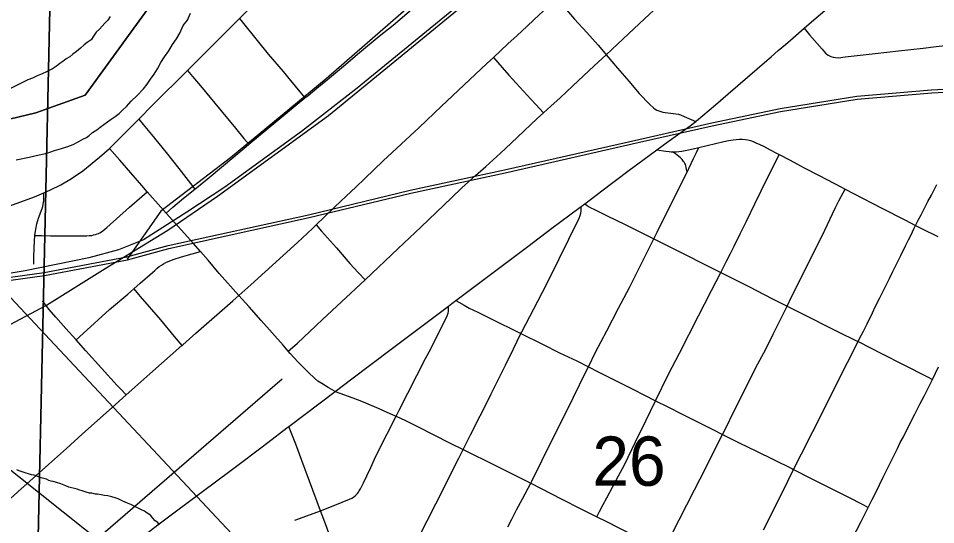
# Model space of a CAD drawing. Extents: x 0 to 34, y 0 to 22.
# Drawn here: x 5.405 to 6.184, y 17.843 to 18.273 of the extents above; entities that cross this region are included whole.
import ezdxf

# ---------------------------------------------------------------- set-up
doc = ezdxf.new("R2010")
doc.units = 0
for name, color, linetype in [('GM_X_City_Street', 7, 'Continuous'), ('GM_X_County_Road', 7, 'Continuous'), ('GM_X_Major_River', 7, 'Continuous'), ('GM_X_Minor_River', 7, 'Continuous'), ('GM_X_Rail_Line', 7, 'Continuous'), ('GM_X_Section', 7, 'Continuous'), ('GM_X_Section_Text', 7, 'Continuous'), ('GM_X_State_Route', 7, 'Continuous'), ('GM_X_Township_Road', 7, 'Continuous'), ('SH_Text', 7, 'Continuous')]:
    doc.layers.add(name, color=color, linetype=linetype)

msp = doc.modelspace()

# ---------------------------------------------------------------- linework, layer by layer
at = {"layer": 'GM_X_City_Street'}
msp.add_line((5.48249, 18.16259), (5.50731, 18.18755), dxfattribs=at)
for points in [[(5.59291, 18.27288), (5.59552, 18.2755), (5.60608, 18.28599), (5.62442, 18.30455), (5.63292, 18.31275), (5.64184, 18.32135), (5.65835, 18.33812), (5.66747, 18.34738), (5.67636, 18.35627)], [(5.59248, 18.03782), (5.60256, 18.04679), (5.64216, 18.0827), (5.65479, 18.09465), (5.65798, 18.09772), (5.66509, 18.10454), (5.67403, 18.11317), (5.68349, 18.12213), (5.69171, 18.12987), (5.69952, 18.13711), (5.71503, 18.15208), (5.7455, 18.18048), (5.7644, 18.19847), (5.80287, 18.23437), (5.80869, 18.23986), (5.82096, 18.25144), (5.82871, 18.25859), (5.83691, 18.26609), (5.84317, 18.27203), (5.84727, 18.27575), (5.85443, 18.28252), (5.85622, 18.2842), (5.86229, 18.28992)], [(5.63431, 17.99043), (5.63979, 17.99526), (5.64213, 17.99732), (5.65266, 18.00702), (5.66356, 18.01721), (5.69953, 18.05091), (5.72782, 18.07778), (5.74686, 18.09566), (5.77331, 18.12104), (5.78185, 18.12918), (5.79333, 18.13962), (5.80223, 18.14738), (5.8146, 18.15867), (5.82363, 18.167), (5.84588, 18.18813), (5.85125, 18.19297), (5.8574, 18.19852), (5.86521, 18.20564), (5.87612, 18.21581), (5.88505, 18.2244), (5.89409, 18.2328), (5.9043, 18.24227), (5.91889, 18.2558), (5.93707, 18.27274), (5.96005, 18.29459)], [(5.53054, 18.10776), (5.53639, 18.11275), (5.54541, 18.12043), (5.55493, 18.12816), (5.56713, 18.13807), (5.59866, 18.16423), (5.60091, 18.16614), (5.62372, 18.18537), (5.64847, 18.20551), (5.65113, 18.20766), (5.6587, 18.21396), (5.66771, 18.2213), (5.68115, 18.23247), (5.6948, 18.24404), (5.71165, 18.25787), (5.72337, 18.26736), (5.73903, 18.28064)], [(5.86892, 18.28232), (5.87745, 18.27248), (5.88791, 18.26099), (5.89748, 18.25033), (5.9035, 18.24319), (5.9043, 18.24227), (5.91399, 18.23094), (5.91996, 18.22394), (5.92354, 18.21973), (5.93248, 18.20944), (5.94141, 18.19994), (5.94454, 18.19708), (5.94589, 18.19608), (5.94753, 18.19517), (5.94906, 18.19451), (5.95083, 18.19397), (5.95251, 18.19358), (5.95437, 18.19326), (5.96366, 18.19208), (5.96571, 18.19165), (5.96749, 18.19108), (5.97069, 18.18972), (5.98042, 18.18562)], [(5.54878, 18.22883), (5.56611, 18.246), (5.59291, 18.27288)], [(5.59291, 18.27288), (5.59637, 18.26863), (5.60807, 18.25431), (5.61737, 18.24263), (5.62994, 18.22797), (5.63624, 18.22024), (5.64404, 18.21084), (5.64847, 18.20551)], [(6.07262, 18.2647), (6.07723, 18.25926), (6.08774, 18.24688), (6.09083, 18.24363), (6.09288, 18.24199), (6.09524, 18.24067), (6.09714, 18.24006), (6.0991, 18.23975), (6.10168, 18.23971), (6.10736, 18.24036), (6.13276, 18.24319), (6.15257, 18.24547), (6.17363, 18.24785), (6.18475, 18.24916), (6.18981, 18.24985), (6.19176, 18.25019), (6.19348, 18.25077), (6.19532, 18.25204), (6.19693, 18.25353)], [(5.80869, 18.23986), (5.81593, 18.23148), (5.82157, 18.22494), (5.84028, 18.20444), (5.84452, 18.20001), (5.85125, 18.19297)], [(5.50731, 18.18755), (5.51929, 18.19961), (5.54878, 18.22883)], [(5.54878, 18.22883), (5.55297, 18.22387), (5.55978, 18.2158), (5.58954, 18.17972), (5.59674, 18.17113), (5.60091, 18.16614)], [(5.50731, 18.18755), (5.51101, 18.18311), (5.51817, 18.17453), (5.53068, 18.15916), (5.54147, 18.14552), (5.55136, 18.13277), (5.55493, 18.12816)], [(5.82084, 17.84123), (5.82419, 17.84783), (5.82834, 17.85566), (5.83323, 17.86489), (5.84029, 17.87822), (5.84127, 17.88006), (5.84987, 17.89744), (5.85944, 17.91679), (5.86833, 17.93474), (5.87658, 17.95142), (5.88724, 17.97296), (5.88928, 17.97708), (5.89544, 17.98954), (5.90492, 18.0077), (5.91489, 18.02688), (5.92411, 18.04464), (5.92838, 18.05301), (5.93424, 18.06446), (5.94487, 18.08579), (5.94779, 18.09163), (5.95799, 18.11223), (5.97307, 18.14244), (5.97456, 18.14561), (5.97852, 18.15396), (5.98102, 18.15924), (5.983, 18.16342)], [(5.9474, 18.16141), (5.95514, 18.16031), (5.95794, 18.15991), (5.95956, 18.15975), (5.96064, 18.15972), (5.96385, 18.15974), (5.96868, 18.16028), (5.97292, 18.16108), (5.97833, 18.16228), (5.983, 18.16342), (6.00433, 18.16862), (6.00832, 18.16947), (6.01236, 18.17008), (6.01484, 18.17037), (6.01742, 18.17045), (6.0199, 18.17044), (6.02252, 18.17019), (6.02479, 18.16982), (6.02691, 18.16925), (6.02924, 18.16847), (6.03166, 18.16752), (6.03485, 18.16602), (6.03792, 18.16453), (6.04357, 18.16157), (6.0492, 18.15862), (6.0514, 18.15747), (6.06075, 18.15257), (6.06946, 18.1479), (6.07269, 18.14618), (6.0853, 18.13954), (6.10432, 18.12974), (6.1075, 18.1281), (6.11448, 18.12449), (6.13865, 18.1118), (6.15796, 18.10189), (6.16721, 18.09728), (6.17236, 18.0947), (6.18616, 18.08791)], [(5.51461, 18.12582), (5.51, 18.1311), (5.49137, 18.15281), (5.48249, 18.16259)], [(5.89645, 17.8498), (5.89878, 17.85419), (5.90192, 17.86009), (5.90503, 17.86594), (5.90977, 17.87486), (5.91489, 17.88451), (5.91984, 17.89386), (5.92933, 17.91332), (5.93812, 17.93131), (5.94639, 17.94827), (5.95745, 17.97093), (5.96669, 17.98878), (5.9829, 18.02058), (5.98789, 18.03025), (5.99393, 18.042), (6.00184, 18.05736), (6.00674, 18.06689), (6.01011, 18.07342), (6.01319, 18.07965), (6.01828, 18.09013), (6.02354, 18.10094), (6.03072, 18.11572), (6.03595, 18.12649), (6.04084, 18.13655), (6.04841, 18.15155), (6.0514, 18.15747)], [(5.97307, 18.14244), (5.97264, 18.14479), (5.97228, 18.14676), (5.97198, 18.14795), (5.97168, 18.149), (5.97125, 18.14994), (5.97066, 18.15093), (5.97021, 18.15163), (5.9696, 18.15242), (5.96901, 18.15322), (5.96821, 18.15405), (5.96718, 18.15501), (5.96619, 18.15588), (5.96483, 18.15695), (5.96332, 18.15803), (5.96064, 18.15972)], [(5.41828, 18.06436), (5.41822, 18.06966), (5.41847, 18.07876), (5.41906, 18.08861), (5.41978, 18.09411), (5.42072, 18.09851), (5.4222, 18.10328), (5.42533, 18.11173), (5.42577, 18.11336), (5.42626, 18.11525), (5.42651, 18.11677), (5.42663, 18.11813), (5.42663, 18.11945), (5.42662, 18.12496)], [(5.41906, 18.08861), (5.42487, 18.08858), (5.43232, 18.08854), (5.46091, 18.08836), (5.46336, 18.08849), (5.46525, 18.08859), (5.46735, 18.08882), (5.46904, 18.08915), (5.47051, 18.08956), (5.47191, 18.09007), (5.47306, 18.09051), (5.47417, 18.09107), (5.47557, 18.09183), (5.47683, 18.09269), (5.48026, 18.09537), (5.49961, 18.11287), (5.50995, 18.1218), (5.51461, 18.12582)], [(5.53054, 18.10776), (5.52599, 18.11283), (5.51461, 18.12582)], [(5.95313, 17.82108), (5.95571, 17.8261), (5.95998, 17.83439), (5.97942, 17.87266), (5.98897, 17.89149), (5.99793, 17.9092), (6.00331, 17.9198), (6.00747, 17.92802), (6.01116, 17.93582), (6.01615, 17.94581), (6.0263, 17.96636), (6.03326, 17.97958), (6.03997, 17.99218), (6.04615, 18.00498), (6.04811, 18.00877), (6.05801, 18.02874), (6.06185, 18.03651), (6.08081, 18.07421), (6.09003, 18.09309), (6.09655, 18.10707), (6.09929, 18.1126), (6.10209, 18.11807), (6.10412, 18.12183), (6.1075, 18.1281)], [(6.038, 17.83868), (6.05394, 17.87018), (6.06363, 17.88984), (6.07031, 17.90338), (6.07987, 17.92232), (6.08916, 17.94074), (6.10044, 17.9631), (6.11832, 17.99855), (6.11967, 18.00122), (6.12295, 18.00746), (6.126, 18.01369), (6.13065, 18.0231), (6.13328, 18.0286), (6.13686, 18.03574), (6.1452, 18.05216), (6.14773, 18.05765), (6.14984, 18.06199), (6.15195, 18.06611), (6.15459, 18.07171), (6.15859, 18.07985), (6.16113, 18.08492), (6.16309, 18.08881), (6.16598, 18.09485), (6.16721, 18.09728), (6.16946, 18.10172), (6.17189, 18.10626), (6.17454, 18.1113), (6.17775, 18.11743), (6.18068, 18.12286), (6.18536, 18.132)], [(5.7451, 17.83202), (5.75959, 17.86084), (5.77927, 17.89954), (5.78294, 17.90685), (5.78928, 17.91948), (5.79745, 17.93551), (5.80301, 17.94656), (5.80679, 17.95432), (5.81308, 17.9671), (5.81876, 17.97864), (5.82558, 17.99251), (5.8319, 18.00534), (5.83272, 18.00701), (5.8462, 18.03288), (5.85415, 18.04833), (5.86443, 18.06884), (5.87258, 18.08558), (5.88147, 18.10329), (5.88241, 18.10569), (5.88281, 18.10752), (5.88316, 18.10947), (5.8831, 18.11196), (5.88306, 18.11335)], [(5.88622, 18.11569), (5.88837, 18.11416), (5.89008, 18.11301), (5.89181, 18.11202), (5.89329, 18.11126), (5.9051, 18.10551), (5.92045, 18.09803), (5.93987, 18.08834), (5.94487, 18.08579), (5.95271, 18.08177), (5.96703, 18.07471), (5.9922, 18.06222), (6.00184, 18.05736), (6.01147, 18.05252), (6.02611, 18.04497), (6.04504, 18.03528), (6.05801, 18.02874), (6.06821, 18.02361), (6.10143, 18.00687), (6.11701, 17.99921), (6.11832, 17.99855), (6.13885, 17.98813), (6.15662, 17.9791), (6.1772, 17.96858), (6.18146, 17.9664)], [(5.55974, 18.07515), (5.55344, 18.08232), (5.53596, 18.10172), (5.53054, 18.10776)], [(5.65798, 18.09772), (5.6626, 18.09248), (5.67532, 18.07808), (5.68675, 18.06499), (5.69383, 18.05718), (5.69953, 18.05091)], [(5.4541, 17.99999), (5.46008, 18.00541), (5.48258, 18.02571), (5.49795, 18.03897), (5.5032, 18.04346), (5.50868, 18.04816), (5.51889, 18.05728), (5.52089, 18.05909), (5.52304, 18.06101), (5.52481, 18.06245), (5.52654, 18.06362), (5.52831, 18.06472), (5.53034, 18.06572), (5.53669, 18.06829), (5.54376, 18.07069), (5.55275, 18.0732), (5.55974, 18.07515)], [(5.59248, 18.03782), (5.57579, 18.05649), (5.56617, 18.06784), (5.55974, 18.07515)], [(5.5032, 18.04346), (5.50709, 18.03869), (5.50866, 18.03677), (5.52569, 18.01694), (5.53755, 18.00283), (5.54403, 17.9953)], [(5.49668, 17.95337), (5.49214, 17.95811), (5.48914, 17.96123), (5.46246, 17.99067), (5.4541, 17.99999), (5.44545, 18.00962), (5.4369, 18.01923), (5.43122, 18.02596), (5.42555, 18.03312)], [(5.63431, 17.99043), (5.62993, 17.99554), (5.61137, 18.01652), (5.60109, 18.02818), (5.59248, 18.03782)], [(5.77663, 18.0334), (5.77919, 18.03196), (5.7837, 18.02939), (5.78813, 18.02709), (5.7953, 18.02348), (5.80556, 18.01849), (5.8319, 18.00534), (5.85038, 17.99632), (5.86482, 17.98917), (5.87933, 17.98216), (5.88928, 17.97708), (5.89822, 17.97254), (5.91291, 17.96529), (5.92708, 17.95804), (5.93684, 17.95306), (5.94639, 17.94827), (5.94733, 17.9478), (5.9557, 17.94374), (5.97013, 17.93647), (5.9824, 17.93026), (5.99506, 17.92395), (6.00331, 17.9198), (6.0175, 17.91266), (6.03202, 17.90541), (6.04654, 17.89834), (6.06202, 17.89066), (6.06363, 17.88984), (6.07852, 17.88229), (6.09616, 17.87349), (6.10912, 17.86693), (6.12295, 17.85986), (6.12697, 17.8578)], [(5.63996, 17.84694), (5.64693, 17.84957), (5.66174, 17.85497), (5.66682, 17.85695), (5.68002, 17.86211), (5.68631, 17.86463), (5.68834, 17.86562), (5.68963, 17.86646), (5.69104, 17.86744), (5.69213, 17.86849), (5.69306, 17.86947), (5.694, 17.87072), (5.69465, 17.87179), (5.69566, 17.87343), (5.69655, 17.87513), (5.69823, 17.8787), (5.70106, 17.88469), (5.7044, 17.89176), (5.70765, 17.89867), (5.71098, 17.9057), (5.72599, 17.93512), (5.72862, 17.94029), (5.75106, 17.98425), (5.75538, 17.99249), (5.76934, 18.0205), (5.77012, 18.02275), (5.77042, 18.02432), (5.77054, 18.02564), (5.77043, 18.02874)], [(5.67421, 17.95622), (5.6681, 17.95955), (5.66272, 17.96303), (5.65952, 17.9651), (5.65649, 17.96746), (5.65154, 17.97226), (5.64803, 17.97577), (5.64274, 17.98103), (5.63603, 17.98843), (5.63431, 17.99043)], [(5.67421, 17.95622), (5.68929, 17.95087), (5.69296, 17.94938), (5.69793, 17.94731), (5.71136, 17.9417), (5.71797, 17.93862), (5.72267, 17.93658), (5.72599, 17.93512)], [(5.72599, 17.93512), (5.73386, 17.93143), (5.74409, 17.92642), (5.77189, 17.91235), (5.78294, 17.90685)], [(5.70396, 17.74064), (5.69946, 17.75219), (5.69487, 17.7644), (5.6926, 17.77035), (5.69107, 17.77444), (5.68954, 17.77851), (5.68596, 17.78827), (5.68159, 17.80079), (5.67801, 17.81108), (5.67363, 17.8229), (5.66974, 17.83339), (5.66669, 17.84162), (5.66174, 17.85497), (5.64595, 17.89758), (5.64064, 17.9115), (5.63674, 17.92143), (5.63473, 17.92654)], [(5.78294, 17.90685), (5.81024, 17.89325), (5.83969, 17.87853), (5.84029, 17.87822)], [(5.84029, 17.87822), (5.8661, 17.86514), (5.88298, 17.85664), (5.89645, 17.8498)], [(5.89645, 17.8498), (5.90404, 17.84595), (5.92788, 17.83392), (5.94139, 17.82699), (5.95313, 17.82108)]]:
    msp.add_lwpolyline(points, dxfattribs=at)
at = {"layer": 'GM_X_County_Road'}
for points in [[(5.42662, 18.12496), (5.43234, 18.12738), (5.4412, 18.13177), (5.45026, 18.13707), (5.45997, 18.14369), (5.47391, 18.15519), (5.48249, 18.16259)], [(5.09582, 18.06236), (5.12563, 18.0648), (5.18258, 18.06906), (5.203, 18.07089), (5.22892, 18.07371), (5.25167, 18.07685), (5.28228, 18.08205), (5.3011, 18.08596), (5.32826, 18.09252), (5.35042, 18.0986), (5.37239, 18.1053), (5.39771, 18.1138), (5.41865, 18.1216), (5.42662, 18.12496)], [(5.54403, 17.9953), (5.5447, 17.99589), (5.55595, 18.00568), (5.58724, 18.03317), (5.59248, 18.03782)], [(5.49668, 17.95337), (5.50141, 17.95755), (5.51667, 17.97125), (5.54403, 17.9953)], [(5.32326, 17.79778), (5.34929, 17.82095), (5.36829, 17.83793), (5.38483, 17.853), (5.40466, 17.87091), (5.4176, 17.88255), (5.43056, 17.89417), (5.44588, 17.90782), (5.45927, 17.91988), (5.48745, 17.9452), (5.49668, 17.95337)]]:
    msp.add_lwpolyline(points, dxfattribs=at)
at = {"layer": 'GM_X_Major_River'}
for points in [[(5.4032, 18.15284), (5.41427, 18.15522), (5.42268, 18.15728), (5.42955, 18.15863), (5.43568, 18.16075), (5.44181, 18.16249), (5.44717, 18.16426), (5.45177, 18.16604), (5.456, 18.16821), (5.45986, 18.17039), (5.46293, 18.17184), (5.46526, 18.17368), (5.46798, 18.17627), (5.47183, 18.17845), (5.47455, 18.18066), (5.48384, 18.18764), (5.48731, 18.18983), (5.4908, 18.1924), (5.49391, 18.19536), (5.49702, 18.19832), (5.50093, 18.20278), (5.50599, 18.20759), (5.51145, 18.21315), (5.51459, 18.21724), (5.51735, 18.22135), (5.5205, 18.22583), (5.52328, 18.23032), (5.52607, 18.23557), (5.52923, 18.24042), (5.53278, 18.24565), (5.53594, 18.25089), (5.53948, 18.25574), (5.54227, 18.2606), (5.54508, 18.26699), (5.54862, 18.27146), (5.55143, 18.27746)], [(5.4032, 18.15284), (5.41427, 18.15522), (5.42268, 18.15728), (5.42955, 18.15863), (5.43568, 18.16075), (5.44181, 18.16249), (5.44717, 18.16426), (5.45177, 18.16604), (5.456, 18.16821), (5.45986, 18.17039), (5.46293, 18.17184), (5.46526, 18.17368), (5.46798, 18.17627), (5.47183, 18.17845), (5.47455, 18.18066), (5.48384, 18.18764), (5.48731, 18.18983), (5.4908, 18.1924), (5.49391, 18.19536), (5.49702, 18.19832), (5.50093, 18.20278), (5.50599, 18.20759), (5.51145, 18.21315), (5.51459, 18.21724), (5.51735, 18.22135), (5.5205, 18.22583), (5.52328, 18.23032), (5.52607, 18.23557), (5.52923, 18.24042), (5.53278, 18.24565), (5.53594, 18.25089), (5.53948, 18.25574), (5.54227, 18.2606), (5.54508, 18.26699), (5.54862, 18.27146), (5.55143, 18.27746)], [(5.48298, 18.27464), (5.48101, 18.27165), (5.47866, 18.26905), (5.47632, 18.26645), (5.47397, 18.26385)], [(5.48298, 18.27464), (5.48101, 18.27165), (5.47866, 18.26905), (5.47632, 18.26645), (5.47397, 18.26385)], [(5.47397, 18.26385), (5.47125, 18.26126), (5.46889, 18.2579), (5.46691, 18.25491), (5.46344, 18.25272), (5.4611, 18.2505), (5.458, 18.24792), (5.45451, 18.24497), (5.45141, 18.24277), (5.4487, 18.24056), (5.44561, 18.23874), (5.4429, 18.23653), (5.44019, 18.2347), (5.43748, 18.23249), (5.43401, 18.2303), (5.429, 18.22777), (5.42516, 18.22597), (5.42094, 18.22417), (5.41709, 18.22237), (5.41326, 18.22095), (5.4098, 18.21914), (5.39788, 18.21337)], [(5.47397, 18.26385), (5.47125, 18.26126), (5.46889, 18.2579), (5.46691, 18.25491), (5.46344, 18.25272), (5.4611, 18.2505), (5.458, 18.24792), (5.45451, 18.24497), (5.45141, 18.24277), (5.4487, 18.24056), (5.44561, 18.23874), (5.4429, 18.23653), (5.44019, 18.2347), (5.43748, 18.23249), (5.43401, 18.2303), (5.429, 18.22777), (5.42516, 18.22597), (5.42094, 18.22417), (5.41709, 18.22237), (5.41326, 18.22095), (5.4098, 18.21914), (5.39788, 18.21337)]]:
    msp.add_lwpolyline(points, dxfattribs=at)
at = {"layer": 'GM_X_Minor_River'}
for points in [[(3.74301, 16.33754), (5.62913, 17.96708)], [(5.42908, 17.88175), (5.42682, 17.88218), (5.42456, 17.883), (5.42079, 17.88424), (5.41853, 17.88505), (5.41626, 17.88549), (5.41362, 17.88632), (5.41173, 17.88674), (5.40835, 17.88797), (5.40571, 17.8888), (5.40383, 17.8896)], [(5.52497, 17.84286), (5.5235, 17.84479), (5.52126, 17.84637), (5.51942, 17.84869), (5.5172, 17.85103), (5.51459, 17.85299), (5.51235, 17.85457), (5.50972, 17.85577), (5.50634, 17.85738), (5.5041, 17.85858), (5.50072, 17.86018), (5.49771, 17.8614), (5.49395, 17.86301), (5.48982, 17.86502), (5.48718, 17.86584), (5.48454, 17.86667), (5.48115, 17.86752), (5.47812, 17.86797), (5.47547, 17.86842), (5.47244, 17.86887), (5.47055, 17.86892), (5.46753, 17.86976), (5.46563, 17.86981), (5.46261, 17.87064), (5.45922, 17.87187), (5.45733, 17.8723), (5.45508, 17.87311), (5.4479, 17.87481), (5.44527, 17.87602), (5.44114, 17.87764), (5.43737, 17.87888), (5.43473, 17.87971), (5.43284, 17.88013), (5.43095, 17.88056), (5.42908, 17.88175)]]:
    msp.add_lwpolyline(points, dxfattribs=at)
at = {"layer": 'GM_X_Rail_Line'}
for points in [[(5.35859, 17.99218), (5.42907, 18.02958), (5.47881, 18.06061), (5.53193, 18.09333), (5.57421, 18.12212), (5.66865, 18.1905), (5.79548, 18.29488), (5.96696, 18.4394), (6.03151, 18.50107), (6.06989, 18.54586), (6.10653, 18.586), (6.14549, 18.66395), (6.16949, 18.71125), (6.26238, 18.89432), (6.28506, 18.94027), (6.30716, 18.97169), (6.33624, 18.99728), (6.40021, 19.03917), (6.84508, 19.29222), (7.76682, 19.80066)], [(6.16926, 18.7118), (6.16192, 18.71544), (6.09429, 18.59005), (5.80873, 18.34581), (5.66662, 18.22164), (5.58516, 18.15477), (5.52623, 18.10931), (5.49752, 18.06868)], [(5.97495, 18.45163), (5.79508, 18.29756), (5.69294, 18.21372), (5.64547, 18.17693), (5.58053, 18.12987), (5.54806, 18.1085), (5.51148, 18.08507), (5.49011, 18.07644), (5.46483, 18.06966), (5.41099, 18.05856), (5.36989, 18.05198), (5.27741, 18.04232), (5.20466, 18.0376), (5.14075, 18.03267), (5.11521, 18.02753)], [(5.35106, 18.04678), (5.42697, 18.05726), (5.49719, 18.07056), (5.53225, 18.08015), (5.65152, 18.10637), (5.73788, 18.12707), (5.81793, 18.14439), (5.93217, 18.17031), (5.99402, 18.1844), (6.05215, 18.19648), (6.1174, 18.20707), (6.18087, 18.21236), (6.22876, 18.21488), (6.43848, 18.20909), (6.70994, 18.20004), (7.11057, 18.18722), (7.54287, 18.1734)], [(5.35138, 18.04432), (5.42737, 18.05481), (5.49775, 18.06813), (5.53284, 18.07774), (5.65207, 18.10395), (5.73843, 18.12465), (5.81847, 18.14196), (5.93272, 18.16789), (5.99455, 18.18197), (6.05261, 18.19404), (6.1177, 18.2046), (6.18104, 18.20988), (6.22879, 18.21239), (6.43841, 18.20661), (6.70986, 18.19756), (7.11049, 18.18474), (7.54279, 18.17091)]]:
    msp.add_lwpolyline(points, dxfattribs=at)
at = {"layer": 'GM_X_Section'}
for points in [[(4.43788, 18.43754), (5.43503, 18.42215), (5.41251, 17.40958), (4.41097, 17.43188)], [(5.43503, 18.42215), (6.44087, 18.40636), (6.41184, 17.39355), (5.41251, 17.40958)]]:
    msp.add_lwpolyline(points, close=True, dxfattribs=at)
at = {"layer": 'GM_X_State_Route'}
for points in [[(5.95776, 18.16903), (5.96505, 18.17423), (5.97561, 18.18187), (5.98042, 18.18562), (5.98099, 18.18606), (5.99718, 18.19954), (6.00799, 18.20889), (6.02443, 18.22315), (6.04086, 18.23733), (6.04273, 18.23894), (6.04455, 18.24057), (6.05059, 18.24584), (6.05672, 18.25099), (6.06328, 18.25663), (6.07262, 18.2647), (6.07688, 18.26839), (6.09611, 18.28503), (6.10887, 18.29581), (6.11112, 18.29776)], [(5.89807, 18.12451), (5.89965, 18.12568), (5.92394, 18.14408), (5.93543, 18.1526), (5.9474, 18.16141), (5.95695, 18.16845), (5.95776, 18.16903)], [(5.67421, 17.95622), (5.68843, 17.96702), (5.72169, 17.99208), (5.77043, 18.02874), (5.77335, 18.03094), (5.77663, 18.0334), (5.83795, 18.07949), (5.8583, 18.09483), (5.8812, 18.11197), (5.88306, 18.11335), (5.88622, 18.11569), (5.89807, 18.12451)], [(6.10948, 17.8235), (6.12089, 17.84588), (6.12697, 17.8578), (6.1303, 17.86434), (6.13333, 17.87028), (6.13978, 17.88347), (6.14307, 17.89033), (6.14698, 17.89827), (6.15176, 17.90774), (6.15426, 17.91275), (6.1569, 17.91763), (6.1602, 17.92419), (6.16649, 17.93694), (6.17085, 17.94533), (6.17467, 17.95271), (6.17806, 17.95946), (6.18146, 17.9664), (6.18679, 17.97725)], [(5.59145, 17.89367), (5.61101, 17.90847), (5.61695, 17.91295), (5.63323, 17.92541), (5.63473, 17.92654), (5.67421, 17.95622)], [(5.36628, 17.69414), (5.3847, 17.72074), (5.39784, 17.73971), (5.4031, 17.74669), (5.40834, 17.75291), (5.41265, 17.75747), (5.41811, 17.76263), (5.42484, 17.76822), (5.43619, 17.77695), (5.46455, 17.79819), (5.48886, 17.81652), (5.50374, 17.82775), (5.52342, 17.84294), (5.5384, 17.85407), (5.56038, 17.87036), (5.58575, 17.88936), (5.59145, 17.89367)]]:
    msp.add_lwpolyline(points, dxfattribs=at)
at = {"layer": 'GM_X_Township_Road'}
for points in [[(5.36178, 18.179), (5.42, 18.19301), (5.46178, 18.20783), (5.52265, 18.29183), (5.59844, 18.40112), (5.70565, 18.52822), (5.80443, 18.65249), (5.89173, 18.74684), (6.02505, 18.80214), (6.20324, 18.83103)], [(6.20324, 18.83103), (6.02505, 18.80214), (5.89173, 18.74684), (5.80443, 18.65249), (5.70565, 18.52822), (5.59844, 18.40112), (5.52265, 18.29183), (5.46178, 18.20783), (5.42, 18.19301), (5.36178, 18.179)]]:
    msp.add_lwpolyline(points, dxfattribs=at)
at = {"layer": 'SH_Text'}
msp.add_line((5.08107, 18.14149), (5.93202, 17.46601), dxfattribs=at)
msp.add_lwpolyline([(5.93202, 17.46601), (5.20653, 18.24084)], dxfattribs=at)

# ---------------------------------------------------------------- texts
at = {"layer": 'GM_X_Section_Text'}
msp.add_text('26', height=0.041856, rotation=0.00001, dxfattribs=at).set_placement((5.89264, 17.87614))

doc.saveas('drawing.dxf')
